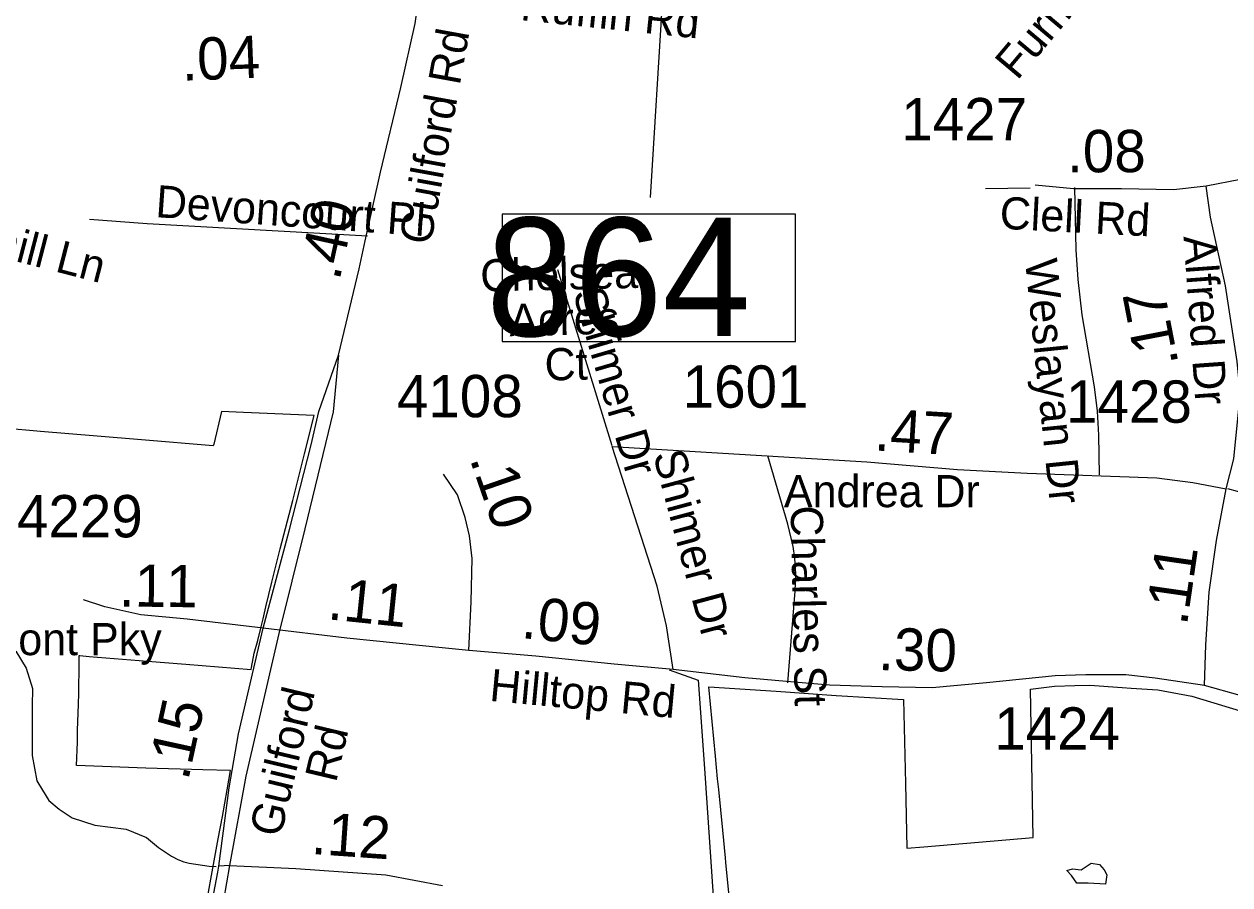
# Model space of a CAD drawing. Extents: x 1662474 to 1856135, y 779280 to 917889.
# Drawn here: x 1727341 to 1730904, y 833752 to 836296 of the extents above; entities that cross this region are included whole.
import ezdxf

# ---------------------------------------------------------------- set-up
doc = ezdxf.new("R2010")
doc.units = 0
for name, color, linetype in [('Exist Boundary Political City Limit New', 7, 'Continuous'), ('Exist Hydrographic Pond Under 1500 Sq Ft', 7, 'Continuous'), ('Exist Road Non-System Type 51', 7, 'Continuous'), ('Exist Road Non-System Type 51 Label', 7, 'Continuous'), ('Exist Road Primary Interstate Structure Standard Bridge Number Label', 7, 'Continuous'), ('Exist Road Secondary Mileage Hundredths English Label', 7, 'Continuous'), ('Exist Road Secondary Mileage Tenths English Label', 7, 'Continuous'), ('Exist Road Secondary Type 51 Attributed', 7, 'Continuous'), ('Exist Road Secondary Type 51 Divided Attributed', 7, 'Continuous'), ('Exist Road Secondary Type 51 Label', 7, 'Continuous'), ('Exist Road Secondary Type 51 Number Label', 7, 'Continuous'), ('Map Preparation Boundary City Limit Buffer Line', 7, 'Continuous')]:
    doc.layers.add(name, color=color, linetype=linetype)

msp = doc.modelspace()

# ---------------------------------------------------------------- linework, layer by layer
at = {"layer": 'Exist Boundary Political City Limit New'}
for points in [[(1727883, 833714.1), (1727892.8, 833769), (1727907, 833845), (1727914.4, 833887.9), (1727927.2, 833954.2), (1727941.5, 834033), (1727951.1, 834089.8), (1727869.8, 834092.2), (1727700.8, 834097.2), (1727624.5, 834099.6), (1727496.6, 834105.5), (1727498.9, 834174), (1727499.5, 834209.9), (1727501.6, 834285.6), (1727502.9, 834318.6), (1727504.4, 834405.2), (1727504.4, 834429.8), (1727506.4, 834429.6), (1727533.5, 834427.4), (1727705.8, 834413.5), (1727819.6, 834404.2), (1728012.2, 834388.7), (1728013.4, 834394.1), (1728021.6, 834437.4), (1728031.6, 834474.8), (1728040.1, 834506.7), (1728047.6, 834538.2), (1728055.9, 834573.5), (1728073.5, 834647.2), (1728098.4, 834745.2), (1728135, 834888.4), (1728170, 835026.4), (1728198.9, 835139.4), (1727989.5, 835148.2), (1727924.9, 835150.9), (1727901.6, 835054.6), (1727900.4, 835049.2), (1727687.9, 835067.1), (1727557.4, 835078.1), (1727389.9, 835092.2), (1727280.5, 835101.4)], [(1729436.6, 833601.2), (1729415.2, 833818.7), (1729414, 833831.9), (1729405.8, 833914.4), (1729393.8, 834033.8), (1729390.5, 834065.9), (1729384.1, 834132.5), (1729364.8, 834337.9), (1729563.8, 834324.2), (1729740.8, 834312), (1729940.2, 834299.6), (1729945.8, 834051.8), (1729949.5, 833860.8), (1730000, 833865), (1730323.1, 833892.3), (1730314.8, 834331), (1730386.1, 834339.4), (1730446.2, 834341.2), (1730490.8, 834342.5), (1730585.6, 834335.7), (1730612.5, 834333.8), (1730690.9, 834328.4), (1730792.2, 834310), (1731022.4, 834240.4)]]:
    msp.add_lwpolyline(points, dxfattribs=at)
at = {"layer": 'Exist Hydrographic Pond Under 1500 Sq Ft'}
msp.add_lwpolyline([(1730536.9, 833754.1), (1730485.4, 833757.8), (1730452.4, 833757.8), (1730435.8, 833779.9), (1730422.9, 833794.6), (1730439.5, 833800.1), (1730465.2, 833796.4), (1730494.6, 833816.6), (1730518.5, 833812.9), (1730533.2, 833796.4), (1730540.6, 833781.7), (1730536.9, 833754.1)], dxfattribs=at)
at = {"layer": 'Exist Road Non-System Type 51'}
for p, q in [((1730313.6, 835811), (1730181.9, 835809)), ((1728917.5, 835570.7), (1729077.9, 835050.4)), ((1731060, 834878.9), (1730898, 834922.1))]:
    msp.add_line(p, q, dxfattribs=at)
for points in [[(1730444.8, 835812.9), (1730448.8, 835628.4), (1730454.5, 835540.8), (1730467.1, 835437.1), (1730502.9, 835224.2), (1730511.8, 835152.2), (1730516.1, 835080.9), (1730518, 834963.9)], [(1728356.1, 835669.1), (1727704.6, 835705.4), (1727534.4, 835718.7)], [(1729597.9, 834349.7), (1729620.1, 834620.2), (1729621.4, 834670.7), (1729618.9, 834718.2), (1729614.1, 834752.4), (1729598.1, 834817.9), (1729539, 835020.5)], [(1727316.8, 834442.6), (1727347.2, 834392.6), (1727366.6, 834332.9), (1727364.9, 834280.9), (1727365.6, 834134.2), (1727379.2, 834059.9), (1727395.8, 834031.9), (1727414.6, 834001.9), (1727444.9, 833975.7), (1727483.4, 833949.9), (1727550.1, 833928.9), (1727642.8, 833916.4), (1727703.1, 833892.5), (1727738.6, 833863.1), (1727776.9, 833837.6), (1727778.8, 833836.4), (1727795.5, 833827.2), (1727813.4, 833820.6), (1727829.5, 833816.9), (1727888.1, 833807.4), (1727908.8, 833806.4)], [(1729247.1, 834387.2), (1729333.2, 834356.8), (1729352.2, 834096.2), (1729377.6, 833719.2), (1729384.6, 833565.4)]]:
    msp.add_lwpolyline(points, dxfattribs=at)
at = {"layer": 'Exist Road Primary Interstate Structure Standard Bridge Number Label'}
msp.add_line((1729343.2, 838289.2), (1729191.6, 835782.9), dxfattribs=at)
msp.add_lwpolyline([(1729620.7, 835733.9), (1728754.2, 835733.9), (1728754.2, 835358.2), (1729620.7, 835358.2)], close=True, dxfattribs=at)
at = {"layer": 'Exist Road Secondary Type 51 Attributed'}
msp.add_line((1727948.3, 833809.9), (1727916.3, 833807.1), dxfattribs=at)
for points in [[(1728270.7, 835317.7), (1728331.6, 835573), (1728349.6, 835655.1), (1728394.1, 835858.4), (1728454.4, 836107.9), (1728497.2, 836297.7), (1728523.5, 836480.9)], [(1731616.4, 835836.4), (1731466.7, 835837.5), (1731226.1, 835854.4), (1731100.1, 835854.4), (1731020.6, 835851.4), (1730935.6, 835836.9), (1730834.5, 835816.6)], [(1730834.5, 835816.6), (1730737.4, 835805.6), (1730584.3, 835808.9), (1730442.3, 835808.5), (1730328.5, 835819.4)], [(1730893.7, 834922.1), (1730916.3, 835010.7), (1730932.1, 835170.1), (1730930.6, 835248.2), (1730925.6, 835298.5), (1730891.5, 835522.1), (1730847.3, 835725.3), (1730834.5, 835816.6)], [(1729259.2, 834388.5), (1729239.5, 834517.5), (1729211.7, 834634.6), (1729079.3, 835047.5), (1729831.8, 835002.4), (1730099.2, 834980.1), (1730305.4, 834969), (1730688, 834955.5), (1730794.8, 834941.5), (1730893.7, 834922.1)], [(1728655.5, 834445.3), (1728662.5, 834588.7), (1728665.1, 834717), (1728657.4, 834783.7), (1728644.6, 834837.6), (1728621.5, 834904.4), (1728580.4, 834965.9)], [(1730828.7, 834341.3), (1730833.3, 834461.9), (1730842.8, 834617.2), (1730864.9, 834770.3), (1730893.7, 834922.1)], [(1728047.8, 834510.4), (1727823.6, 834537.2), (1727686, 834550.2), (1727579.6, 834573.6), (1727517.3, 834594.3)], [(1728655.5, 834445.3), (1728586.7, 834451.4), (1728295.4, 834481.7), (1728047.8, 834510.4)], [(1729259.2, 834388.5), (1729085.2, 834404.3), (1728853.6, 834427.9), (1728655.5, 834445.3)], [(1730828.7, 834341.3), (1730683.5, 834363.3), (1730596.9, 834372.7), (1730479, 834373.3), (1730388.1, 834370), (1730184.6, 834349.6), (1730024.7, 834334.6), (1729876.4, 834337.7), (1729721.3, 834342.7), (1729616.3, 834350.8), (1729470.8, 834364.5), (1729259.2, 834388.5)], [(1731145.1, 834253.2), (1730828.7, 834341.3)], [(1727948.3, 833809.9), (1728144.5, 833800.5), (1728410.6, 833782.1), (1728578.1, 833750.4)]]:
    msp.add_lwpolyline(points, dxfattribs=at)
at = {"layer": 'Exist Road Secondary Type 51 Divided Attributed'}
for points in [[(1728270.7, 835317.7), (1728254.4, 835149.9), (1728170.7, 834804), (1728094.5, 834495.2), (1727996.4, 834073.8), (1727948.3, 833809.9)], [(1728047.8, 834510.4), (1728124.7, 834798.5), (1728189.2, 835052.5), (1728211.8, 835151.3), (1728270.7, 835317.7)], [(1727916.3, 833807.1), (1727947.6, 834039.5), (1727975.1, 834198.7), (1728047.8, 834510.4)], [(1727948.3, 833809.9), (1727903.7, 833553.6), (1727879.7, 833430.1), (1727853.6, 833332.6), (1727811.1, 833181.7), (1727787.7, 833119.9)], [(1727747.9, 833132.3), (1727808.3, 833299.7), (1727845.4, 833423.2), (1727871.5, 833567.4), (1727914, 833789.7), (1727916.3, 833807.1)]]:
    msp.add_lwpolyline(points, dxfattribs=at)
at = {"layer": 'Map Preparation Boundary City Limit Buffer Line'}
for points in [[(1727883, 833714.1), (1727892.8, 833769), (1727907, 833845), (1727914.4, 833887.9), (1727927.2, 833954.2), (1727941.5, 834033), (1727951.1, 834089.8), (1727869.8, 834092.2), (1727700.8, 834097.2), (1727624.5, 834099.6), (1727496.6, 834105.5), (1727498.9, 834174), (1727499.5, 834209.9), (1727501.6, 834285.6), (1727502.9, 834318.6), (1727504.4, 834405.2), (1727504.4, 834429.8), (1727506.4, 834429.6), (1727533.5, 834427.4), (1727705.8, 834413.5), (1727819.6, 834404.2), (1728012.2, 834388.7), (1728013.4, 834394.1), (1728021.6, 834437.4), (1728031.6, 834474.8), (1728040.1, 834506.7), (1728047.6, 834538.2), (1728055.9, 834573.5), (1728073.5, 834647.2), (1728098.4, 834745.2), (1728135, 834888.4), (1728170, 835026.4), (1728198.9, 835139.4), (1727989.5, 835148.2), (1727924.9, 835150.9), (1727901.6, 835054.6), (1727900.4, 835049.2), (1727687.9, 835067.1), (1727557.4, 835078.1), (1727389.9, 835092.2), (1727280.5, 835101.4)], [(1729436.6, 833601.2), (1729415.2, 833818.7), (1729414, 833831.9), (1729405.8, 833914.4), (1729393.8, 834033.8), (1729390.5, 834065.9), (1729384.1, 834132.5), (1729364.8, 834337.9), (1729563.8, 834324.2), (1729740.8, 834312), (1729940.2, 834299.6), (1729945.8, 834051.8), (1729949.5, 833860.8), (1730000, 833865), (1730323.1, 833892.3), (1730314.8, 834331), (1730386.1, 834339.4), (1730446.2, 834341.2), (1730490.8, 834342.5), (1730585.6, 834335.7), (1730612.5, 834333.8), (1730690.9, 834328.4), (1730792.2, 834310), (1731022.4, 834240.4)]]:
    msp.add_lwpolyline(points, dxfattribs=at)

# ---------------------------------------------------------------- texts
at = {"layer": 'Exist Road Non-System Type 51 Label'}
for s, rotation, p in [('Devoncourt Pl', 355.9485, (1727727.9, 835725.5)), ('Flowerhill Ln', 345.5215, (1726876.3, 835708.5)), ('Weslayan Dr', 275.8285, (1730298.7, 835597.6)), ('Shimer Dr', 286.351, (1728962.4, 835501.8)), ('Charles St', 271.2312, (1729606.1, 834872.3))]:
    msp.add_text(s, height=95, rotation=rotation, dxfattribs=at).set_placement(p)
at = {"layer": 'Exist Road Primary Interstate Structure Standard Bridge Number Label'}
msp.add_text('864', height=350, dxfattribs=at).set_placement((1728706.8, 835373.8))
at = {"layer": 'Exist Road Secondary Mileage Hundredths English Label'}
for s, rotation, p in [('.17', 100.9488, (1730753.1, 835292.1)), ('.10', 289.1013, (1728657.2, 835011.4)), ('.11', 81.786, (1730776.9, 834516.1))]:
    msp.add_text(s, height=125, rotation=rotation, dxfattribs=at).set_placement(p)
at = {"layer": 'Exist Road Secondary Mileage Tenths English Label'}
for s, rotation, p in [('.04', 2.252, (1727808.5, 836128.2)), ('.08', 0.1599, (1730423.4, 835857.7)), ('.40', 77.6476, (1728272.9, 835535)), ('.47', 356.5663, (1729851.7, 835036.1)), ('.11', 359.3821, (1727621.1, 834574.9)), ('.11', 354.0685, (1728235.6, 834537.4)), ('.09', 354.1959, (1728808, 834482)), ('.30', 358.8251, (1729864.2, 834387.1)), ('.15', 77.6879, (1727825.9, 834057.7)), ('.12', 356.0447, (1728187.7, 833843.8))]:
    msp.add_text(s, height=125, rotation=rotation, dxfattribs=at).set_placement(p)
at = {"layer": 'Exist Road Secondary Type 51 Label'}
for s, rotation, p in [('Furman Pl', 49.9135, (1730275.8, 836127.2)), ('Ruffin Rd', 354.0798, (1728805.9, 836307.8)), ('Guilford Rd', 79.6791, (1728542.4, 835640)), ('Clell Rd', 357.0585, (1730222.4, 835691.3)), ('Alfred Dr', 274.1015, (1730767, 835668)), ('Chelsea', 1.3671, (1728690.3, 835505.1)), (' Acres', 1.3671, (1728740.8, 835372.6)), (' Ct', 1.3671, (1728845.1, 835241.4)), ('Shimer Dr', 285.0511, (1729199.1, 835024.1)), ('Hilltop Rd', 354.6729, (1728714.3, 834296.3)), ('Guilford ', 76.6326, (1728098.8, 833889.7)), ('Rd', 76.6326, (1728262.8, 834052))]:
    msp.add_text(s, height=95, rotation=rotation, dxfattribs=at).set_placement(p)
for s, p in [('Andrea Dr', (1729586.4, 834868.3)), ('Piedmont Pky', (1726964.1, 834431))]:
    msp.add_text(s, height=95, dxfattribs=at).set_placement(p)
at = {"layer": 'Exist Road Secondary Type 51 Number Label'}
for s, p in [('1427', (1729933.2, 835952.4)), ('1601', (1729287.3, 835162.2)), ('4108', (1728442.9, 835134.1)), ('1428', (1730420.1, 835117.8)), ('4229', (1727320.1, 834779.2)), ('1424', (1730207.8, 834151.9))]:
    msp.add_text(s, height=125, dxfattribs=at).set_placement(p)

doc.saveas('drawing.dxf')
